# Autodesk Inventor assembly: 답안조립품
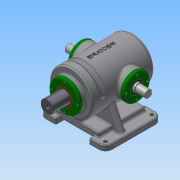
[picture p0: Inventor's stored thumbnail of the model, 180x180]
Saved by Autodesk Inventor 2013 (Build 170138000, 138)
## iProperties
Created: 2018-06
Part Number: 답안조립품
Document SubType Name: Assembly
Designer: Administrator
Author: Administrator
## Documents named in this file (13)
- C:\Users\Administrator\Desktop\380628V1004\답안조립품.iam
- C:\Users\Administrator\Desktop\380628V1004\본체.ipt
- C:\Users\Administrator\Desktop\380628V1004\가변스프링.ipt
- C:\Users\Administrator\Desktop\380628V1004\베어링 6205.ipt
- 베어링 6205.ipt
- C:\Users\Administrator\Desktop\380628V1004\볼트 M4.ipt
- C:\Users\Administrator\Desktop\380628V1004\부시.ipt
- C:\Users\Administrator\Desktop\380628V1004\슬라이드 커버.ipt
- C:\Users\Administrator\Desktop\380628V1004\슬라이드.ipt
- C:\Users\Administrator\Desktop\380628V1004\오일실.ipt
- 오일실.ipt
- C:\Users\Administrator\Desktop\380628V1004\축 커버.ipt
- C:\Users\Administrator\Desktop\380628V1004\편심축.ipt
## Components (1 placed, 1 different names)
1. 가변스프링:1
